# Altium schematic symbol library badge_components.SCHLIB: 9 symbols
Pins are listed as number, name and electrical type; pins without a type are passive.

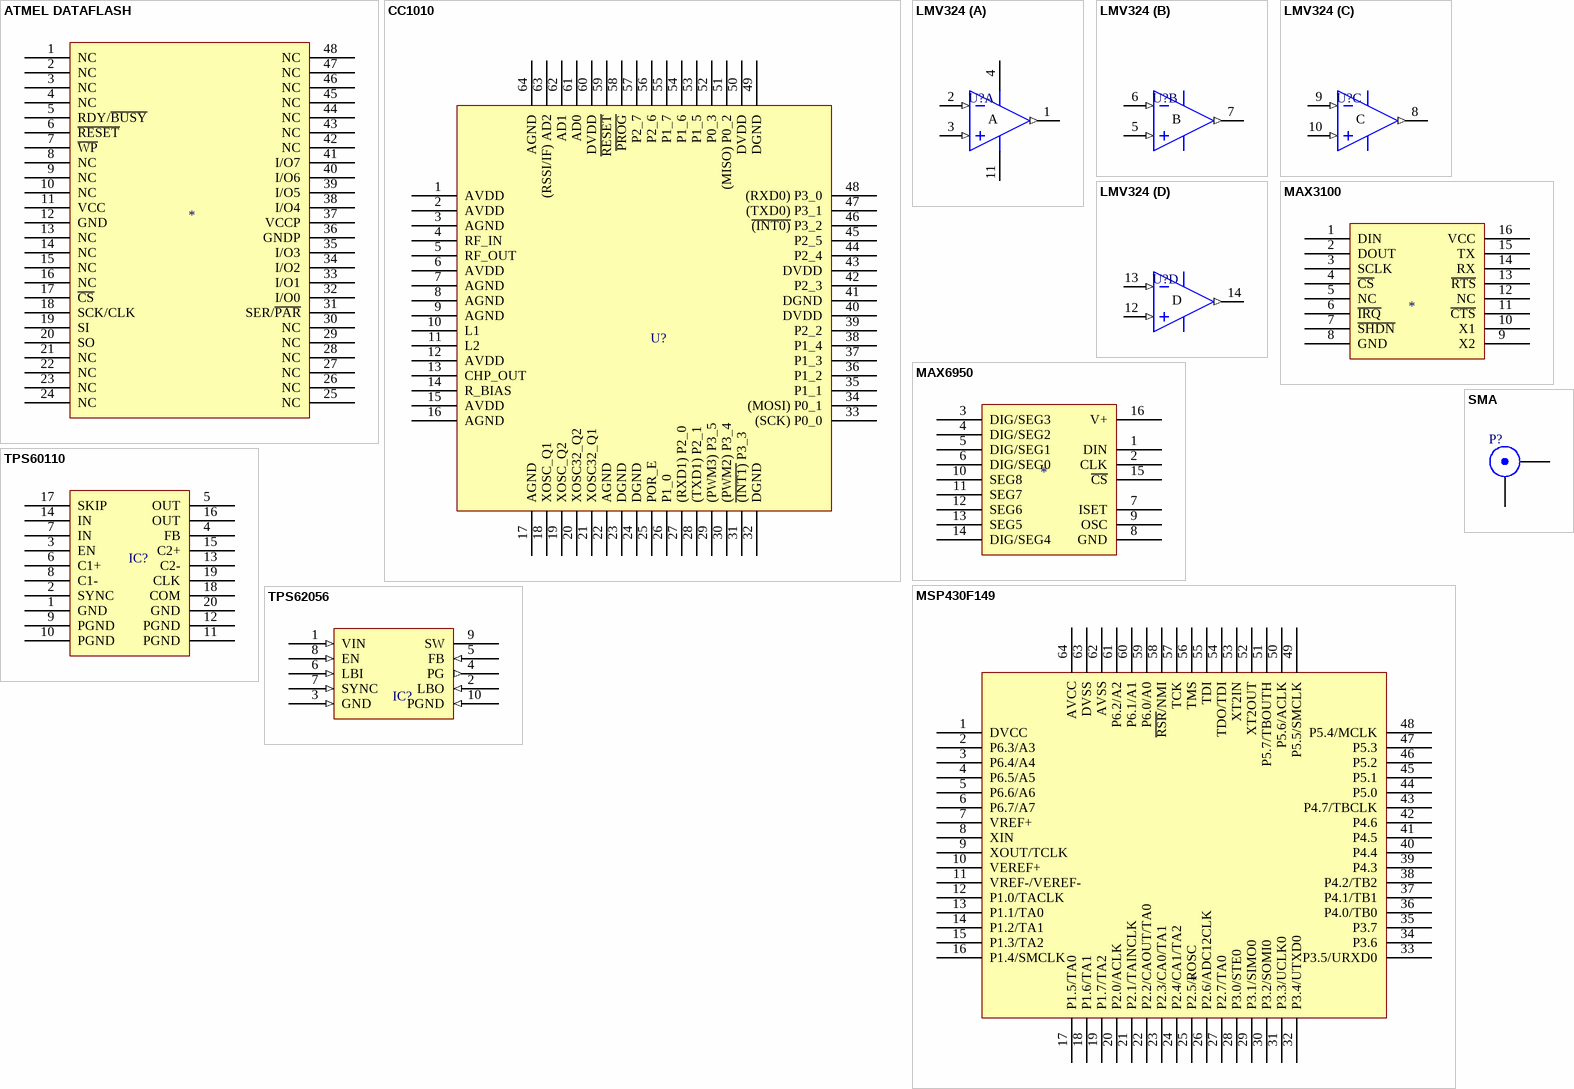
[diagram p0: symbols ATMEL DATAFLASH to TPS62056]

## ATMEL DATAFLASH
designator *
pins: 1 NC, 2 NC, 3 NC, 4 NC, 5 RDY/~{BUSY}, 6 ~{RESET}, 7 ~{WP}, 8 NC, 9 NC, 10 NC, 11 VCC, 12 GND, 13 NC, 14 NC, 15 NC, 16 NC, 17 ~{CS}, 18 SCK/CLK, 19 SI, 20 SO, 21 NC, 22 NC, 23 NC, 24 NC, 25 NC, 26 NC, 27 NC, 28 NC, 29 NC, 30 NC, 31 SER/~{PAR}, 32 I/O0, 33 I/O1, 34 I/O2, 35 I/O3, 36 GNDP, 37 VCCP, 38 I/O4, 39 I/O5, 40 I/O6, 41 I/O7, 42 NC, 43 NC, 44 NC, 45 NC, 46 NC, 47 NC, 48 NC

## CC1010
designator U?
pins: 1 AVDD, 2 AVDD, 3 AGND, 4 RF_IN, 5 RF_OUT, 6 AVDD, 7 AGND, 8 AGND, 9 AGND, 10 L1, 11 L2, 12 AVDD, 13 CHP_OUT, 14 R_BIAS, 15 AVDD, 16 AGND, 17 AGND, 18 XOSC_Q1, 19 XOSC_Q2, 20 XOSC32_Q2, 21 XOSC32_Q1, 22 AGND, 23 DGND, 24 DGND, 25 POR_E, 26 P1_0, 27 (RXD1) P2_0, 28 (TXD1) P2_1, 29 (PWM3) P3_5, 30 (PWM2) P3_4, 31 ~{(INT1)} P3_3, 32 DGND, 33 (SCK) P0_0, 34 (MOSI) P0_1, 35 P1_1, 36 P1_2, 37 P1_3, 38 P1_4, 39 P2_2, 40 DVDD, 41 DGND, 42 P2_3, 43 DVDD, 44 P2_4, 45 P2_5, 46 ~{(INT0)} P3_2, 47 (TXD0) P3_1, 48 (RXD0) P3_0, 49 DGND, 50 DVDD, 51 (MISO) P0_2, 52 P0_3, 53 P1_5, 54 P1_6, 55 P1_7, 56 P2_6, 57 P2_7, 58 ~{PROG}, 59 ~{RESET}, 60 DVDD, 61 AD0, 62 AD1, 63 (RSSI/IF) AD2, 64 AGND

## LMV324
designator U?
Quad Low Voltage Op Amp; Manufacturer: Analog Devices; Class I: Amplifier; Class II: Operational Amplifier
footprint DIP-14/X1.4
part A pins: 1 OUT (out), 2 IN- (in), 3 IN+ (in), 4 V+ (power), 11 V- (power)
part B pins: 5 IN+ (in), 6 IN- (in), 7 OUT (out)
part C pins: 8 OUT (out), 9 IN- (in), 10 IN+ (in)
part D pins: 12 IN+ (in), 13 IN- (in), 14 OUT (out)

## MAX3100
designator *
pins: 1 DIN, 2 DOUT, 3 SCLK, 4 ~{CS}, 5 NC, 6 ~{IRQ}, 7 ~{SHDN}, 8 GND, 9 X2, 10 X1, 11 ~{CTS}, 12 NC, 13 ~{RTS}, 14 RX, 15 TX, 16 VCC

## MAX6950
designator *
pins: 1 DIN, 2 CLK, 3 DIG/SEG3, 4 DIG/SEG2, 5 DIG/SEG1, 6 DIG/SEG0, 7 ISET, 8 GND, 9 OSC, 10 SEG8, 11 SEG7, 12 SEG6, 13 SEG5, 14 DIG/SEG4, 15 ~{CS}, 16 V+

## MSP430F149
designator *
pins: 1 DVCC, 2 P6.3/A3, 3 P6.4/A4, 4 P6.5/A5, 5 P6.6/A6, 6 P6.7/A7, 7 VREF+, 8 XIN, 9 XOUT/TCLK, 10 VEREF+, 11 VREF-/VEREF-, 12 P1.0/TACLK, 13 P1.1/TA0, 14 P1.2/TA1, 15 P1.3/TA2, 16 P1.4/SMCLK, 17 P1.5/TA0, 18 P1.6/TA1, 19 P1.7/TA2, 20 P2.0/ACLK, 21 P2.1/TAINCLK, 22 P2.2/CAOUT/TA0, 23 P2.3/CA0/TA1, 24 P2.4/CA1/TA2, 25 P2.5/ROSC, 26 P2.6/ADC12CLK, 27 P2.7/TA0, 28 P3.0/STE0, 29 P3.1/SIMO0, 30 P3.2/SOMI0, 31 P3.3/UCLK0, 32 P3.4/UTXD0, 33 P3.5/URXD0, 34 P3.6, 35 P3.7, 36 P4.0/TB0, 37 P4.1/TB1, 38 P4.2/TB2, 39 P4.3, 40 P4.4, 41 P4.5, 42 P4.6, 43 P4.7/TBCLK, 44 P5.0, 45 P5.1, 46 P5.2, 47 P5.3, 48 P5.4/MCLK, 49 P5.5/SMCLK, 50 P5.6/ACLK, 51 P5.7/TBOUTH, 52 XT2OUT, 53 XT2IN, 54 TDO/TDI, 55 TDI, 56 TMS, 57 TCK, 58 ~{RSR}/NMI, 59 P6.0/A0, 60 P6.1/A1, 61 P6.2/A2, 62 AVSS, 63 DVSS, 64 AVCC

## SMA
designator P?
SMA Straight Connector; Manufacturer: Generic Components; Class II: RF Coaxial
footprint SMB_V-RJ45
signal-integrity model Connector
pins: 1 X, 2 Y

## TPS60110
designator IC?
TI CHARGE PUMP DC/DC CONVERTER
pins: 1 GND, 2 SYNC, 3 EN, 4 FB, 5 OUT, 6 C1+, 7 IN, 8 C1-, 9 PGND, 10 PGND, 11 PGND, 12 PGND, 13 C2-, 14 IN, 15 C2+, 16 OUT, 17 SKIP, 18 COM, 19 CLK, 20 GND

## TPS62056
designator IC?
TI STEP DOWN CONVERTER
footprint Model Name (Model Description)
pins: 1 VIN (in), 2 LBO (in), 3 GND (in), 4 PG (out), 5 FB (in), 6 LBI (in), 7 SYNC (in), 8 EN (in), 9 SW (power), 10 PGND (in)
